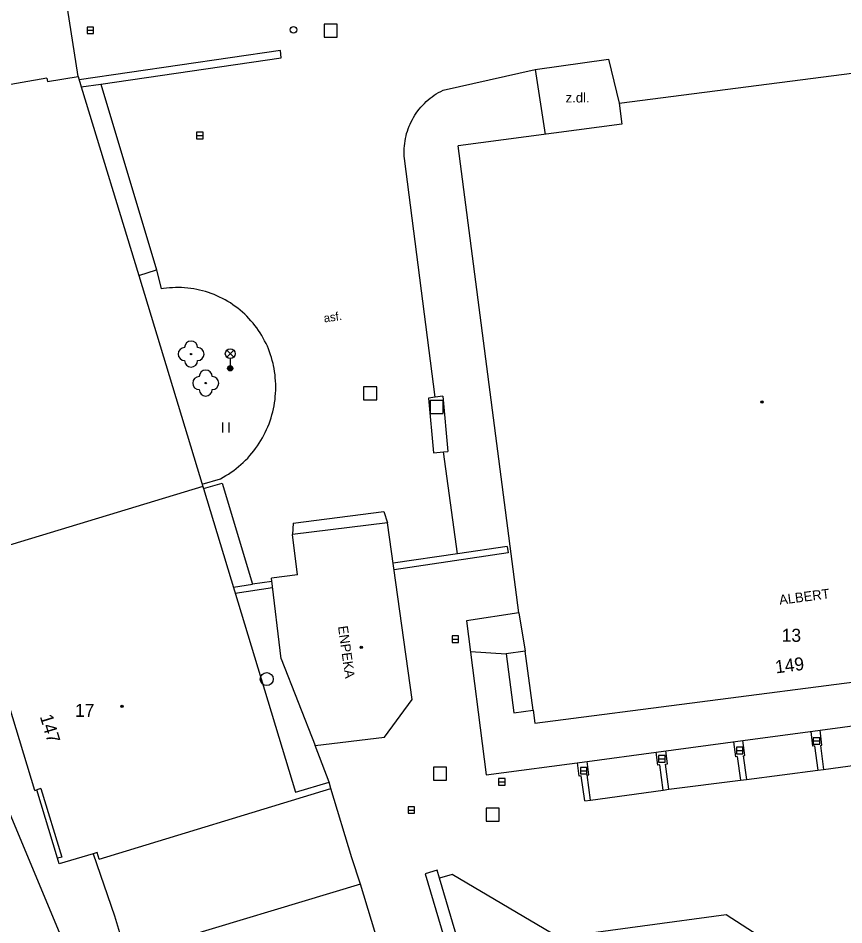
# Model space of a CAD drawing. Extents: x -641829 to -641525, y -1114855 to -1114359.
# Drawn here: x -641768.9 to -641705.6, y -1114670.9 to -1114601.3 of the extents above; entities that cross this region are included whole.
import ezdxf

# ---------------------------------------------------------------- set-up
doc = ezdxf.new("R2010")
doc.units = 0
for name, color, linetype in [('Vrstva 1', 7, 'Continuous'), ('Vrstva 10', 7, 'Continuous'), ('Vrstva 11', 7, 'Continuous'), ('Vrstva 22', 7, 'Continuous'), ('Vrstva 26', 7, 'Continuous'), ('Vrstva 27', 7, 'Continuous'), ('Vrstva 28', 7, 'Continuous'), ('Vrstva 33', 7, 'Continuous'), ('Vrstva 36', 7, 'Continuous'), ('Vrstva 39', 7, 'Continuous'), ('Vrstva 40', 7, 'Continuous'), ('Vrstva 41', 7, 'Continuous'), ('Vrstva 46', 7, 'Continuous'), ('Vrstva 47', 7, 'Continuous'), ('Vrstva 5', 7, 'Continuous'), ('Vrstva 8', 7, 'Continuous')]:
    doc.layers.add(name, color=color, linetype=linetype)

msp = doc.modelspace()

# ---------------------------------------------------------------- linework, layer by layer
at = {"layer": 'Vrstva 1'}
msp.add_line((-641812.64, -1114559.36), (-641689.21, -1114854.71), dxfattribs=at)
at = {"layer": 'Vrstva 10'}
for p, q in [((-641736.3, -1114606.87), (-641729.24, -1114605.28)), ((-641736.84, -1114607.16), (-641736.67, -1114607.06)), ((-641736.67, -1114607.06), (-641736.5, -1114606.97)), ((-641736.5, -1114606.97), (-641736.3, -1114606.87)), ((-641737.75, -1114607.89), (-641737.61, -1114607.75)), ((-641737.61, -1114607.75), (-641737.46, -1114607.62)), ((-641737.46, -1114607.62), (-641737.31, -1114607.5)), ((-641737.31, -1114607.5), (-641737.16, -1114607.38)), ((-641737.16, -1114607.38), (-641737, -1114607.27)), ((-641737, -1114607.27), (-641736.84, -1114607.16)), ((-641738.26, -1114608.47), (-641738.14, -1114608.32)), ((-641738.14, -1114608.32), (-641738.01, -1114608.17)), ((-641738.01, -1114608.17), (-641737.88, -1114608.02)), ((-641737.88, -1114608.02), (-641737.75, -1114607.89)), ((-641738.76, -1114609.3), (-641738.67, -1114609.13)), ((-641738.67, -1114609.13), (-641738.58, -1114608.96)), ((-641738.58, -1114608.96), (-641738.48, -1114608.79)), ((-641738.48, -1114608.79), (-641738.37, -1114608.63)), ((-641738.37, -1114608.63), (-641738.26, -1114608.47)), ((-641739.05, -1114610.02), (-641738.99, -1114609.84)), ((-641738.99, -1114609.84), (-641738.92, -1114609.65)), ((-641738.92, -1114609.65), (-641738.85, -1114609.48)), ((-641738.85, -1114609.48), (-641738.76, -1114609.3)), ((-641739.2, -1114610.58), (-641739.16, -1114610.39)), ((-641739.16, -1114610.39), (-641739.11, -1114610.21)), ((-641739.11, -1114610.21), (-641739.05, -1114610.02)), ((-641739.29, -1114611.35), (-641739.28, -1114611.16)), ((-641739.28, -1114611.16), (-641739.26, -1114610.97)), ((-641739.26, -1114610.97), (-641739.23, -1114610.77)), ((-641739.23, -1114610.77), (-641739.2, -1114610.58)), ((-641739.3, -1114611.55), (-641739.29, -1114611.35)), ((-641739.3, -1114611.74), (-641739.3, -1114611.55)), ((-641739.29, -1114611.94), (-641739.3, -1114611.74)), ((-641739.27, -1114612.13), (-641739.29, -1114611.94)), ((-641736.92, -1114630.45), (-641739.27, -1114612.13)), ((-641758.3, -1114620.67), (-641757.95, -1114622.13)), ((-641757.77, -1114622.1), (-641757.95, -1114622.13)), ((-641757.54, -1114622.07), (-641757.77, -1114622.1)), ((-641757.31, -1114622.05), (-641757.54, -1114622.07)), ((-641757.08, -1114622.04), (-641757.31, -1114622.05)), ((-641756.84, -1114622.03), (-641757.08, -1114622.04)), ((-641756.61, -1114622.03), (-641756.84, -1114622.03)), ((-641756.38, -1114622.03), (-641756.61, -1114622.03)), ((-641756.15, -1114622.05), (-641756.38, -1114622.03)), ((-641755.91, -1114622.07), (-641756.15, -1114622.05)), ((-641755.68, -1114622.1), (-641755.91, -1114622.07)), ((-641755.45, -1114622.13), (-641755.68, -1114622.1)), ((-641755.22, -1114622.17), (-641755.45, -1114622.13)), ((-641755, -1114622.22), (-641755.22, -1114622.17)), ((-641754.77, -1114622.28), (-641755, -1114622.22)), ((-641754.54, -1114622.34), (-641754.77, -1114622.28)), ((-641754.32, -1114622.41), (-641754.54, -1114622.34)), ((-641754.1, -1114622.49), (-641754.32, -1114622.41)), ((-641753.89, -1114622.57), (-641754.1, -1114622.49)), ((-641753.67, -1114622.66), (-641753.89, -1114622.57)), ((-641753.46, -1114622.76), (-641753.67, -1114622.66)), ((-641753.25, -1114622.86), (-641753.46, -1114622.76)), ((-641753.04, -1114622.97), (-641753.25, -1114622.86)), ((-641752.84, -1114623.09), (-641753.04, -1114622.97)), ((-641752.64, -1114623.21), (-641752.84, -1114623.09)), ((-641752.45, -1114623.34), (-641752.64, -1114623.21)), ((-641752.26, -1114623.48), (-641752.45, -1114623.34)), ((-641752.07, -1114623.62), (-641752.26, -1114623.48)), ((-641751.89, -1114623.76), (-641752.07, -1114623.62)), ((-641751.72, -1114623.91), (-641751.89, -1114623.76)), ((-641751.54, -1114624.07), (-641751.72, -1114623.91)), ((-641751.38, -1114624.23), (-641751.54, -1114624.07)), ((-641751.21, -1114624.4), (-641751.38, -1114624.23)), ((-641751.06, -1114624.57), (-641751.21, -1114624.4)), ((-641750.9, -1114624.75), (-641751.06, -1114624.57)), ((-641750.76, -1114624.93), (-641750.9, -1114624.75)), ((-641750.62, -1114625.12), (-641750.76, -1114624.93)), ((-641750.48, -1114625.31), (-641750.62, -1114625.12)), ((-641750.35, -1114625.5), (-641750.48, -1114625.31)), ((-641750.23, -1114625.7), (-641750.35, -1114625.5)), ((-641750.12, -1114625.9), (-641750.23, -1114625.7)), ((-641750.01, -1114626.11), (-641750.12, -1114625.9)), ((-641749.9, -1114626.31), (-641750.01, -1114626.11)), ((-641749.8, -1114626.53), (-641749.9, -1114626.31)), ((-641749.71, -1114626.74), (-641749.8, -1114626.53)), ((-641749.63, -1114626.96), (-641749.71, -1114626.74)), ((-641749.55, -1114627.18), (-641749.63, -1114626.96)), ((-641749.48, -1114627.4), (-641749.55, -1114627.18)), ((-641749.42, -1114627.62), (-641749.48, -1114627.4)), ((-641749.36, -1114627.85), (-641749.42, -1114627.62)), ((-641749.33, -1114628.01), (-641749.36, -1114627.85)), ((-641749.28, -1114628.24), (-641749.33, -1114628.01)), ((-641749.24, -1114628.48), (-641749.28, -1114628.24)), ((-641749.21, -1114628.72), (-641749.24, -1114628.48)), ((-641749.19, -1114628.96), (-641749.21, -1114628.72)), ((-641749.17, -1114629.19), (-641749.19, -1114628.96)), ((-641749.16, -1114629.43), (-641749.17, -1114629.19)), ((-641749.17, -1114630.15), (-641749.16, -1114629.91)), ((-641749.16, -1114629.67), (-641749.16, -1114629.43)), ((-641749.16, -1114629.91), (-641749.16, -1114629.67)), ((-641749.25, -1114630.87), (-641749.21, -1114630.63)), ((-641749.21, -1114630.63), (-641749.19, -1114630.39)), ((-641749.19, -1114630.39), (-641749.17, -1114630.15)), ((-641749.39, -1114631.57), (-641749.33, -1114631.34)), ((-641749.33, -1114631.34), (-641749.29, -1114631.1)), ((-641749.29, -1114631.1), (-641749.25, -1114630.87)), ((-641749.59, -1114632.26), (-641749.52, -1114632.03)), ((-641749.52, -1114632.03), (-641749.45, -1114631.8)), ((-641749.45, -1114631.8), (-641749.39, -1114631.57)), ((-641749.86, -1114632.93), (-641749.76, -1114632.71)), ((-641749.76, -1114632.71), (-641749.67, -1114632.48)), ((-641749.67, -1114632.48), (-641749.59, -1114632.26)), ((-641750.18, -1114633.57), (-641750.07, -1114633.36)), ((-641750.07, -1114633.36), (-641749.96, -1114633.14)), ((-641749.96, -1114633.14), (-641749.86, -1114632.93)), ((-641750.7, -1114634.37), (-641750.56, -1114634.18)), ((-641750.56, -1114634.18), (-641750.43, -1114633.98)), ((-641750.43, -1114633.98), (-641750.3, -1114633.77)), ((-641750.3, -1114633.77), (-641750.18, -1114633.57)), ((-641751.15, -1114634.93), (-641751, -1114634.75)), ((-641751, -1114634.75), (-641750.85, -1114634.56)), ((-641750.85, -1114634.56), (-641750.7, -1114634.37)), ((-641735.22, -1114642.46), (-641736.27, -1114634.63)), ((-641752.01, -1114635.77), (-641751.83, -1114635.61)), ((-641751.83, -1114635.61), (-641751.65, -1114635.45)), ((-641751.65, -1114635.45), (-641751.48, -1114635.28)), ((-641751.48, -1114635.28), (-641751.31, -1114635.11)), ((-641751.31, -1114635.11), (-641751.15, -1114634.93)), ((-641752.78, -1114636.34), (-641752.58, -1114636.2)), ((-641752.58, -1114636.2), (-641752.38, -1114636.06)), ((-641752.38, -1114636.06), (-641752.19, -1114635.92)), ((-641752.19, -1114635.92), (-641752.01, -1114635.77)), ((-641754.79, -1114637.12), (-641753.4, -1114636.7)), ((-641753.4, -1114636.7), (-641753.19, -1114636.59)), ((-641753.19, -1114636.59), (-641752.98, -1114636.46)), ((-641752.98, -1114636.46), (-641752.78, -1114636.34))]:
    msp.add_line(p, q, dxfattribs=at)
msp.add_lwpolyline([(-641729.24, -1114605.28), (-641723.63, -1114604.49), (-641722.8, -1114607.87)], dxfattribs=at)
at = {"layer": 'Vrstva 11'}
for p, q in [((-641748.79, -1114603.83), (-641764.24, -1114606.08)), ((-641748.73, -1114604.38), (-641748.79, -1114603.83)), ((-641762.59, -1114606.41), (-641748.73, -1114604.38)), ((-641729.24, -1114605.28), (-641728.47, -1114610.27)), ((-641736.92, -1114630.45), (-641737.44, -1114630.52)), ((-641737.44, -1114630.52), (-641737.05, -1114634.7)), ((-641736.34, -1114630.37), (-641736.92, -1114630.45)), ((-641736.34, -1114630.37), (-641735.95, -1114634.6)), ((-641737.05, -1114634.7), (-641736.27, -1114634.63)), ((-641736.27, -1114634.63), (-641735.95, -1114634.6)), ((-641747.82, -1114640.1), (-641740.87, -1114639.21)), ((-641740.87, -1114639.21), (-641740.58, -1114640.09)), ((-641747.82, -1114640.1), (-641747.86, -1114640.97)), ((-641735.22, -1114642.46), (-641740.15, -1114643.19)), ((-641731.33, -1114642.39), (-641740.08, -1114643.69)), ((-641731.4, -1114641.89), (-641735.22, -1114642.46)), ((-641731.4, -1114641.89), (-641731.33, -1114642.39)), ((-641749.46, -1114644.58), (-641750.95, -1114644.8)), ((-641749.4, -1114645.07), (-641752.26, -1114645.5)), ((-641707.93, -1114657.22), (-641708.08, -1114656.1)), ((-641707.25, -1114657.15), (-641707.39, -1114656)), ((-641713.85, -1114658.04), (-641714, -1114656.89)), ((-641713.17, -1114657.94), (-641713.32, -1114656.8)), ((-641707.36, -1114657.17), (-641707.25, -1114657.15)), ((-641707.36, -1114657.17), (-641707.11, -1114659.02)), ((-641719.84, -1114658.69), (-641719.97, -1114657.69)), ((-641719.09, -1114658.59), (-641719.22, -1114657.59)), ((-641707.81, -1114657.2), (-641707.93, -1114657.22)), ((-641707.81, -1114657.2), (-641707.55, -1114659.08)), ((-641725.86, -1114659.52), (-641725.99, -1114658.5)), ((-641725.12, -1114659.42), (-641725.25, -1114658.4)), ((-641713.74, -1114658.02), (-641713.85, -1114658.04)), ((-641713.74, -1114658.02), (-641713.48, -1114659.85)), ((-641713.29, -1114657.96), (-641713.17, -1114657.94)), ((-641713.29, -1114657.96), (-641713.04, -1114659.79)), ((-641707.11, -1114659.02), (-641701.61, -1114658.28)), ((-641719.69, -1114658.67), (-641719.84, -1114658.69)), ((-641719.42, -1114660.6), (-641719.69, -1114658.67)), ((-641719.24, -1114658.61), (-641719.09, -1114658.59)), ((-641718.98, -1114660.54), (-641719.24, -1114658.61)), ((-641713.04, -1114659.79), (-641707.55, -1114659.08)), ((-641707.55, -1114659.08), (-641707.11, -1114659.02)), ((-641725.71, -1114659.5), (-641725.86, -1114659.52)), ((-641725.44, -1114661.43), (-641725.71, -1114659.5)), ((-641725.27, -1114659.44), (-641725.12, -1114659.42)), ((-641725, -1114661.37), (-641725.27, -1114659.44)), ((-641718.98, -1114660.54), (-641713.48, -1114659.85)), ((-641713.48, -1114659.85), (-641713.04, -1114659.79)), ((-641725, -1114661.37), (-641719.42, -1114660.6)), ((-641719.42, -1114660.6), (-641718.98, -1114660.54)), ((-641725.44, -1114661.43), (-641725, -1114661.37)), ((-641736.77, -1114666.75), (-641737.68, -1114667.04)), ((-641736.59, -1114667.35), (-641736.77, -1114666.75)), ((-641737.68, -1114667.04), (-641735.05, -1114675.92)), ((-641735.61, -1114667.09), (-641736.59, -1114667.35)), ((-641734.13, -1114675.65), (-641736.59, -1114667.35)), ((-641727.43, -1114671.92), (-641735.61, -1114667.09)), ((-641714.58, -1114670.18), (-641727.43, -1114671.92)), ((-641708.25, -1114674.26), (-641714.58, -1114670.18))]:
    msp.add_line(p, q, dxfattribs=at)
at = {"layer": 'Vrstva 22'}
for centre in [(-641755.65, -1114627.13), (-641754.53, -1114629.36)]:
    msp.add_circle(centre, 0.05, dxfattribs=at)
for centre, start, end in [((-641755.65, -1114626.63), 0, 180), ((-641756.15, -1114627.13), 90, 270), ((-641755.15, -1114627.13), 270, 90), ((-641755.65, -1114627.63), 180, 0), ((-641754.53, -1114628.86), 0, 180), ((-641755.03, -1114629.36), 90, 270), ((-641754.03, -1114629.36), 270, 90), ((-641754.53, -1114629.86), 180, 0)]:
    msp.add_arc(centre, 0.5, start, end, dxfattribs=at)
at = {"layer": 'Vrstva 26'}
for points in [[(-641745.45, -1114602.8), (-641744.45, -1114602.8), (-641744.45, -1114601.8), (-641745.45, -1114601.8)], [(-641742.41, -1114630.65), (-641741.41, -1114630.65), (-641741.41, -1114629.65), (-641742.41, -1114629.65)], [(-641737.3, -1114631.69), (-641736.3, -1114631.69), (-641736.3, -1114630.69), (-641737.3, -1114630.69)], [(-641737.04, -1114659.84), (-641736.04, -1114659.84), (-641736.04, -1114658.84), (-641737.04, -1114658.84)], [(-641733.01, -1114662.98), (-641732.01, -1114662.98), (-641732.01, -1114661.98), (-641733.01, -1114661.98)]]:
    msp.add_lwpolyline(points, close=True, dxfattribs=at)
at = {"layer": 'Vrstva 27'}
for p, q in [((-641763.63, -1114602.28), (-641763.13, -1114602.28)), ((-641755.23, -1114610.35), (-641754.73, -1114610.35)), ((-641735.62, -1114649.01), (-641735.12, -1114649.01)), ((-641707.91, -1114656.83), (-641707.41, -1114656.83)), ((-641713.81, -1114657.56), (-641713.31, -1114657.56)), ((-641719.78, -1114658.2), (-641719.28, -1114658.2)), ((-641725.78, -1114659.11), (-641725.28, -1114659.11)), ((-641732.05, -1114659.96), (-641731.55, -1114659.96)), ((-641739, -1114662.13), (-641738.5, -1114662.13))]:
    msp.add_line(p, q, dxfattribs=at)
for points in [[(-641763.63, -1114602.53), (-641763.13, -1114602.53), (-641763.13, -1114602.03), (-641763.63, -1114602.03)], [(-641755.23, -1114610.6), (-641754.73, -1114610.6), (-641754.73, -1114610.1), (-641755.23, -1114610.1)], [(-641735.62, -1114649.26), (-641735.12, -1114649.26), (-641735.12, -1114648.76), (-641735.62, -1114648.76)], [(-641707.91, -1114657.08), (-641707.41, -1114657.08), (-641707.41, -1114656.58), (-641707.91, -1114656.58)], [(-641713.81, -1114657.81), (-641713.31, -1114657.81), (-641713.31, -1114657.31), (-641713.81, -1114657.31)], [(-641719.78, -1114658.45), (-641719.28, -1114658.45), (-641719.28, -1114657.95), (-641719.78, -1114657.95)], [(-641725.78, -1114659.36), (-641725.28, -1114659.36), (-641725.28, -1114658.86), (-641725.78, -1114658.86)], [(-641732.05, -1114660.21), (-641731.55, -1114660.21), (-641731.55, -1114659.71), (-641732.05, -1114659.71)], [(-641739, -1114662.38), (-641738.5, -1114662.38), (-641738.5, -1114661.88), (-641739, -1114661.88)]]:
    msp.add_lwpolyline(points, close=True, dxfattribs=at)
msp.add_circle((-641749.85, -1114652.08), 0.5, dxfattribs=at)
at = {"layer": 'Vrstva 28'}
msp.add_circle((-641747.79, -1114602.24), 0.25, dxfattribs=at)
at = {"layer": 'Vrstva 33'}
for p, q in [((-641752.916, -1114627.37), (-641752.384, -1114626.84)), ((-641752.916, -1114626.84), (-641752.384, -1114627.37)), ((-641752.65, -1114627.48), (-641752.65, -1114628.23))]:
    msp.add_line(p, q, dxfattribs=at)
for centre, radius in [((-641752.65, -1114627.105), 0.375), ((-641752.65, -1114628.23), 0.2), ((-641752.65, -1114628.23), 0.145), ((-641752.65, -1114628.23), 0.0876)]:
    msp.add_circle(centre, radius, dxfattribs=at)
at = {"layer": 'Vrstva 36'}
for p, q in [((-641753.224, -1114633.144), (-641753.224, -1114632.392)), ((-641752.724, -1114633.144), (-641752.724, -1114632.392))]:
    msp.add_line(p, q, dxfattribs=at)
at = {"layer": 'Vrstva 39'}
for centre, radius in [((-641711.85, -1114630.82), 0.09), ((-641711.85, -1114630.82), 0.0398), ((-641742.59, -1114649.64), 0.09), ((-641742.59, -1114649.64), 0.0398), ((-641760.95, -1114654.18), 0.09), ((-641760.95, -1114654.18), 0.0398)]:
    msp.add_circle(centre, radius, dxfattribs=at)
at = {"layer": 'Vrstva 5'}
for p, q in [((-641764.32, -1114605.83), (-641766.14, -1114594.25)), ((-641722.8, -1114607.87), (-641694.37, -1114604.21)), ((-641766.72, -1114605.96), (-641786.41, -1114609.32)), ((-641766.72, -1114605.96), (-641766.68, -1114606.22)), ((-641766.68, -1114606.22), (-641764.32, -1114605.83)), ((-641764.32, -1114605.83), (-641764.08, -1114606.63)), ((-641764.08, -1114606.63), (-641762.59, -1114606.41)), ((-641764.08, -1114606.63), (-641759.67, -1114621.09)), ((-641762.59, -1114606.41), (-641758.3, -1114620.67)), ((-641722.8, -1114607.87), (-641722.59, -1114609.49)), ((-641722.59, -1114609.49), (-641735.16, -1114611.15)), ((-641730.49, -1114647), (-641735.16, -1114611.15)), ((-641759.67, -1114621.09), (-641758.3, -1114620.67)), ((-641759.67, -1114621.09), (-641754.74, -1114637.3)), ((-641754.74, -1114637.3), (-641770.17, -1114641.99)), ((-641754.74, -1114637.3), (-641754.69, -1114637.46)), ((-641754.69, -1114637.46), (-641753.26, -1114637.03)), ((-641754.69, -1114637.46), (-641747.65, -1114660.76)), ((-641753.26, -1114637.03), (-641750.95, -1114644.8)), ((-641740.58, -1114640.09), (-641747.86, -1114640.97)), ((-641738.7, -1114653.65), (-641740.58, -1114640.09)), ((-641747.48, -1114644.08), (-641747.86, -1114640.97)), ((-641767.65, -1114660.62), (-641773.04, -1114642.86)), ((-641747.48, -1114644.08), (-641749.49, -1114644.33)), ((-641748.73, -1114650.53), (-641749.49, -1114644.33)), ((-641752.4, -1114645.02), (-641750.95, -1114644.8)), ((-641730.49, -1114647), (-641734.51, -1114647.6)), ((-641730.49, -1114647), (-641730.01, -1114649.94)), ((-641734.51, -1114647.6), (-641733, -1114659.44)), ((-641734.21, -1114649.97), (-641731.48, -1114650.13)), ((-641730.01, -1114649.94), (-641731.48, -1114650.13)), ((-641731.48, -1114650.13), (-641730.88, -1114654.66)), ((-641729.41, -1114654.46), (-641730.01, -1114649.94)), ((-641729.28, -1114655.46), (-641687.21, -1114650.01)), ((-641748.73, -1114650.53), (-641746.12, -1114657.19)), ((-641740.8, -1114656.53), (-641738.7, -1114653.65)), ((-641730.88, -1114654.66), (-641729.41, -1114654.46)), ((-641729.41, -1114654.46), (-641729.28, -1114655.46)), ((-641707.39, -1114656), (-641702.13, -1114655.3)), ((-641713.32, -1114656.8), (-641707.39, -1114656)), ((-641746.12, -1114657.19), (-641740.8, -1114656.53)), ((-641719.97, -1114657.69), (-641713.32, -1114656.8)), ((-641725.25, -1114658.4), (-641719.97, -1114657.69)), ((-641733, -1114659.44), (-641725.25, -1114658.4)), ((-641767.65, -1114660.62), (-641767.49, -1114660.57)), ((-641767.18, -1114660.48), (-641767.49, -1114660.57)), ((-641765.9, -1114665.83), (-641767.49, -1114660.57)), ((-641767.18, -1114660.48), (-641765.58, -1114665.74)), ((-641762.7, -1114665.9), (-641744.92, -1114660.48)), ((-641747.65, -1114660.76), (-641745.06, -1114660)), ((-641744.92, -1114660.48), (-641745.06, -1114660)), ((-641743.31, -1114665.79), (-641744.92, -1114660.48)), ((-641763.16, -1114665.49), (-641765.77, -1114666.27)), ((-641762.85, -1114665.4), (-641763.16, -1114665.49)), ((-641763.16, -1114665.49), (-641761.53, -1114670.25)), ((-641762.7, -1114665.9), (-641762.85, -1114665.4)), ((-641765.58, -1114665.74), (-641765.9, -1114665.83)), ((-641765.77, -1114666.27), (-641765.9, -1114665.83)), ((-641742.64, -1114667.82), (-641743.31, -1114665.79)), ((-641742.64, -1114667.82), (-641758.27, -1114672.54)), ((-641739.13, -1114679.42), (-641742.64, -1114667.82)), ((-641761.53, -1114670.25), (-641756.29, -1114687.63))]:
    msp.add_line(p, q, dxfattribs=at)
at = {"layer": 'Vrstva 8'}
msp.add_line((-641745.06, -1114660), (-641746.12, -1114657.19), dxfattribs=at)

# ---------------------------------------------------------------- texts
at = {"layer": 'Vrstva 40'}
msp.add_text('asf.', height=0.6499, rotation=8.46226, dxfattribs=at).set_placement((-641745.43, -1114624.71))
at = {"layer": 'Vrstva 41'}
msp.add_text('z.dl.', height=0.75, dxfattribs=at).set_placement((-641726.91, -1114607.82))
for s, height, rotation, p in [('ALBERT', 0.7499, 7.3822, (-641710.48, -1114646.38)), ('ENPEKA', 0.75, 277.88563, (-641744.38, -1114648.04))]:
    msp.add_text(s, height=height, rotation=rotation, dxfattribs=at).set_placement(p)
at = {"layer": 'Vrstva 46'}
for s, p in [('13', (-641710.33, -1114649.22)), ('17', (-641764.56, -1114654.98))]:
    msp.add_text(s, height=1, dxfattribs=at).set_placement(p)
at = {"layer": 'Vrstva 47'}
for s, height, rotation, p in [('149', 0.9999, 7.3822, (-641710.77, -1114651.65)), ('147', 1, 286.85894, (-641767.27, -1114654.95))]:
    msp.add_text(s, height=height, rotation=rotation, dxfattribs=at).set_placement(p)

doc.saveas('drawing.dxf')
